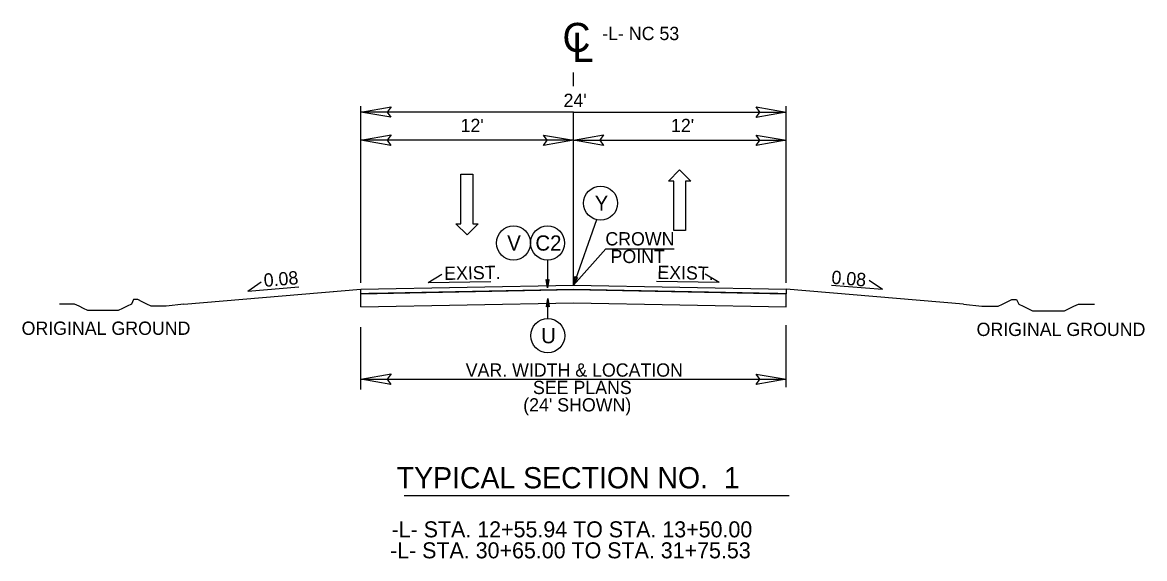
# Model space of a CAD drawing. Extents: x 1548135 to 1549339, y 868664 to 869085.
# Drawn here: x 1548183.5 to 1548246.8, y 868978 to 869008.2 of the extents above; entities that cross this region are included whole.
import ezdxf

# ---------------------------------------------------------------- set-up
doc = ezdxf.new("R2010")
doc.units = 0
for name, color, linetype in [('P_RDY_TC_Pvmt_Asphalt_Base_Course', 7, 'Continuous'), ('Prop Dimension', 7, 'Continuous'), ('Prop Terminator CELL', 7, 'Continuous'), ('Sheet_Data_Field_CELL', 7, 'Continuous'), ('Sheet_Plan', 7, 'Continuous'), ('Sheet_Title_Block_Text', 7, 'Continuous'), ('Typical Grade Point Symbol CELL', 7, 'Continuous'), ('Typical Hinge Slope Arterial CELL', 7, 'Continuous'), ('Typical Hinge Slope Interstate CELL', 7, 'Continuous'), ('Typical Pavement Slope CELL', 7, 'Continuous'), ('Typical Pavement Slope Information CELL', 7, 'Continuous'), ('Typical Shoulder Slope CELL', 7, 'Continuous'), ('Typical Shoulder Slope Information CELL', 7, 'Continuous'), ('Typical Terminator CELL', 7, 'Continuous'), ('Typical Text General CELL', 7, 'Continuous'), ('Typical Text Grade Point CELL', 7, 'Continuous'), ('z - Construction', 7, 'Continuous')]:
    doc.layers.add(name, color=color, linetype=linetype)

msp = doc.modelspace()

# ---------------------------------------------------------------- linework, layer by layer
at = {"layer": 'P_RDY_TC_Pvmt_Asphalt_Base_Course'}
for points in [[(1548204.279, 869002.875), (1548202.592, 869003.165), (1548204.289, 869003.465), (1548204.073, 869003.165)], [(1548224.904, 869003.456), (1548226.592, 869003.165), (1548224.895, 869002.865), (1548225.11, 869003.165)], [(1548204.279, 869001.283), (1548202.592, 869001.574), (1548204.289, 869001.874), (1548204.073, 869001.574)], [(1548212.904, 869001.864), (1548214.592, 869001.574), (1548212.895, 869001.274), (1548213.11, 869001.574)], [(1548216.279, 869001.283), (1548214.592, 869001.574), (1548216.289, 869001.874), (1548216.073, 869001.574)], [(1548224.904, 869001.864), (1548226.592, 869001.574), (1548224.895, 869001.274), (1548225.11, 869001.574)], [(1548204.279, 868987.79), (1548202.592, 868988.081), (1548204.288, 868988.381), (1548204.073, 868988.081)], [(1548224.904, 868988.372), (1548226.592, 868988.081), (1548224.895, 868987.781), (1548225.111, 868988.081)]]:
    msp.add_lwpolyline(points, close=True, dxfattribs=at)
at = {"layer": 'Prop Dimension'}
msp.add_lwpolyline([(1548236.603, 868992.328), (1548237.64, 868992.199), (1548237.9, 868992.199), (1548238.289, 868992.199), (1548238.548, 868992.199), (1548238.808, 868992.328), (1548239.067, 868992.459), (1548239.326, 868992.589), (1548239.586, 868992.589), (1548239.716, 868992.328), (1548239.975, 868992.199), (1548240.235, 868992.069), (1548240.494, 868991.94), (1548240.753, 868991.94), (1548241.013, 868991.94), (1548241.272, 868991.94), (1548241.531, 868991.94), (1548241.791, 868991.94), (1548242.05, 868991.94), (1548242.309, 868991.94), (1548242.569, 868992.069), (1548242.828, 868992.199), (1548243.087, 868992.328), (1548243.477, 868992.328), (1548243.736, 868992.328), (1548243.995, 868992.328)], dxfattribs=at)
at = {"layer": 'Prop Terminator CELL'}
msp.add_lwpolyline([(1548202.592, 868993.162), (1548214.592, 868993.402), (1548226.592, 868993.162), (1548226.592, 868992.912), (1548226.125, 868992.922), (1548225.062, 868992.943), (1548214.592, 868993.152), (1548204.124, 868992.943), (1548204.129, 868992.943), (1548203.043, 868992.921), (1548202.592, 868992.912)], close=True, dxfattribs=at)
at = {"layer": 'Sheet_Data_Field_CELL'}
msp.add_lwpolyline([(1548192.592, 868992.329), (1548191.606, 868992.207), (1548191.36, 868992.207), (1548190.99, 868992.207), (1548190.743, 868992.207), (1548190.497, 868992.329), (1548190.251, 868992.453), (1548190.004, 868992.577), (1548189.758, 868992.577), (1548189.634, 868992.329), (1548189.388, 868992.207), (1548189.141, 868992.083), (1548188.895, 868991.96), (1548188.649, 868991.96), (1548188.402, 868991.96), (1548188.156, 868991.96), (1548187.91, 868991.96), (1548187.663, 868991.96), (1548187.417, 868991.96), (1548187.171, 868991.96), (1548186.924, 868992.083), (1548186.678, 868992.207), (1548186.431, 868992.329), (1548186.061, 868992.329), (1548185.815, 868992.329), (1548185.569, 868992.329)], dxfattribs=at)
at = {"layer": 'Sheet_Plan'}
for p, q in [((1548192.592, 868992.329), (1548202.592, 868993.162)), ((1548236.603, 868992.328), (1548226.592, 868993.162))]:
    msp.add_line(p, q, dxfattribs=at)
at = {"layer": 'Typical Grade Point Symbol CELL'}
for p, q in [((1548214.592, 869004.626), (1548214.592, 869005.395)), ((1548202.592, 868993.522), (1548202.592, 869003.491)), ((1548214.592, 869003.165), (1548202.592, 869003.165)), ((1548214.592, 868993.402), (1548214.592, 869003.165)), ((1548214.592, 869003.165), (1548226.592, 869003.165)), ((1548226.592, 868993.522), (1548226.592, 869003.491)), ((1548214.592, 869001.574), (1548202.592, 869001.574)), ((1548214.592, 869001.574), (1548226.592, 869001.574))]:
    msp.add_line(p, q, dxfattribs=at)
at = {"layer": 'Typical Hinge Slope Arterial CELL'}
msp.add_line((1548216.419, 868995.447), (1548220.268, 868995.447), dxfattribs=at)
at = {"layer": 'Typical Hinge Slope Interstate CELL'}
for p, q in [((1548215.88, 868997.089), (1548214.592, 868993.402)), ((1548213.123, 868994.811), (1548213.123, 868993.249)), ((1548200.592, 868992.996), (1548202.592, 868993.162)), ((1548202.592, 868992.912), (1548214.592, 868993.152)), ((1548214.592, 868993.152), (1548226.592, 868992.912)), ((1548202.592, 868992.162), (1548202.592, 868992.912)), ((1548202.592, 868992.162), (1548214.592, 868992.402)), ((1548213.136, 868991.503), (1548213.136, 868992.637)), ((1548214.592, 868992.402), (1548226.592, 868992.162)), ((1548226.592, 868992.162), (1548226.592, 868992.912))]:
    msp.add_line(p, q, dxfattribs=at)
for points in [[(1548213.204, 868993.718), (1548213.123, 868993.249), (1548213.04, 868993.721), (1548213.123, 868993.661)], [(1548214.822, 868993.818), (1548214.592, 868993.402), (1548214.668, 868993.875), (1548214.727, 868993.791)], [(1548213.055, 868992.168), (1548213.136, 868992.637), (1548213.219, 868992.166), (1548213.136, 868992.226)]]:
    msp.add_lwpolyline(points, close=True, dxfattribs=at)
for centre in [(1548216.115, 868998.022), (1548211.2, 868995.773), (1548213.123, 868995.773), (1548213.136, 868990.541)]:
    msp.add_circle(centre, 0.962, dxfattribs=at)
at = {"layer": 'Typical Pavement Slope CELL'}
msp.add_line((1548202.592, 868993.162), (1548214.592, 868993.402), dxfattribs=at)
at = {"layer": 'Typical Pavement Slope Information CELL'}
for p, q in [((1548206.38, 868993.538), (1548207.163, 868994.012)), ((1548206.38, 868993.538), (1548209.919, 868993.609)), ((1548222.804, 868993.538), (1548219.264, 868993.609)), ((1548222.804, 868993.538), (1548222.021, 868994.012)), ((1548232.033, 868993.14), (1548231.281, 868993.662)), ((1548196.202, 868993.058), (1548196.954, 868993.58)), ((1548196.202, 868993.058), (1548199.085, 868993.299)), ((1548232.033, 868993.14), (1548229.15, 868993.38))]:
    msp.add_line(p, q, dxfattribs=at)
at = {"layer": 'Typical Shoulder Slope CELL'}
msp.add_line((1548216.419, 868995.447), (1548214.592, 868993.402), dxfattribs=at)
at = {"layer": 'Typical Shoulder Slope Information CELL'}
for p, q in [((1548208.238, 868996.858), (1548208.238, 868999.658)), ((1548208.238, 868999.658), (1548208.898, 868999.658)), ((1548208.898, 868999.658), (1548208.898, 868996.858)), ((1548219.955, 868999.272), (1548220.575, 868999.902)), ((1548220.575, 868999.902), (1548221.215, 868999.272)), ((1548220.255, 868999.272), (1548219.955, 868999.272)), ((1548220.255, 868996.472), (1548220.255, 868999.272)), ((1548221.215, 868999.272), (1548220.915, 868999.272)), ((1548220.915, 868999.272), (1548220.915, 868996.472)), ((1548208.578, 868996.228), (1548207.938, 868996.858)), ((1548207.938, 868996.858), (1548208.238, 868996.858)), ((1548209.198, 868996.858), (1548208.578, 868996.228)), ((1548208.898, 868996.858), (1548209.198, 868996.858)), ((1548220.915, 868996.472), (1548220.255, 868996.472))]:
    msp.add_line(p, q, dxfattribs=at)
at = {"layer": 'Typical Terminator CELL'}
for p, q in [((1548226.592, 868987.626), (1548226.592, 868991.129)), ((1548202.592, 868987.511), (1548202.592, 868991.014)), ((1548202.592, 868988.081), (1548226.592, 868988.081)), ((1548205.039, 868981.518), (1548226.76, 868981.518))]:
    msp.add_line(p, q, dxfattribs=at)
at = {"layer": 'Typical Text Grade Point CELL'}
msp.add_line((1548214.592, 868993.402), (1548226.592, 868993.162), dxfattribs=at)

# ---------------------------------------------------------------- texts
at = {"layer": 'Sheet_Data_Field_CELL'}
for p in [(1548183.437, 868990.588), (1548237.339, 868990.523)]:
    msp.add_text('ORIGINAL GROUND', height=0.75, dxfattribs=at).set_placement(p)
at = {"layer": 'Sheet_Title_Block_Text'}
msp.add_text('C', height=1.64, dxfattribs=at).set_placement((1548213.965, 869006.563))
msp.add_text('L', height=1.641, rotation=359.9469, dxfattribs=at).set_placement((1548214.51, 869006.003))
at = {"layer": 'Typical Hinge Slope Arterial CELL'}
msp.add_text('  TYPICAL SECTION NO.  1', height=1.2, dxfattribs=at).set_placement((1548203.722, 868981.92))
at = {"layer": 'Typical Hinge Slope Interstate CELL'}
for s, height, p in [('-L- NC 53', 0.75, (1548216.207, 869007.23)), ('Y', 0.861, (1548215.784, 868997.591)), ('V', 0.861, (1548210.846, 868995.343)), ('C2', 0.8608, (1548212.437, 868995.343)), ('U', 0.861, (1548212.761, 868990.111))]:
    msp.add_text(s, height=height, dxfattribs=at).set_placement(p)
at = {"layer": 'Typical Pavement Slope Information CELL'}
for rotation, p in [(1.14564, (1548207.296, 868993.685)), (358.85436, (1548219.314, 868993.748))]:
    msp.add_text('EXIST.', height=0.75, rotation=rotation, dxfattribs=at).set_placement(p)
at = {"layer": 'Typical Shoulder Slope CELL'}
for s, p in [("24'", (1548214.027, 869003.454)), ("12'", (1548208.214, 869002.035)), ("12'", (1548220.091, 869002.035)), ('CROWN', (1548216.387, 868995.636)), ('POINT', (1548216.678, 868994.642)), ('VAR. WIDTH & LOCATION', (1548208.503, 868988.227)), ('SEE PLANS', (1548212.3, 868987.244)), ("(24' SHOWN)", (1548211.75, 868986.261))]:
    msp.add_text(s, height=0.75, dxfattribs=at).set_placement(p)
at = {"layer": 'Typical Text General CELL'}
for s, p in [('-L- STA. 12+55.94 TO STA. 13+50.00', (1548204.32, 868979.155)), ('-L- STA. 30+65.00 TO STA. 31+75.53', (1548204.232, 868977.97))]:
    msp.add_text(s, height=0.90387, dxfattribs=at).set_placement(p)
at = {"layer": 'z - Construction'}
for rotation, p in [(355.23853, (1548229.125, 868993.478)), (4.76147, (1548197.135, 868993.293))]:
    msp.add_text('0.08', height=0.75, rotation=rotation, dxfattribs=at).set_placement(p)

doc.saveas('drawing.dxf')
